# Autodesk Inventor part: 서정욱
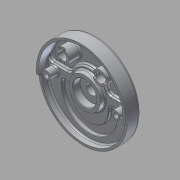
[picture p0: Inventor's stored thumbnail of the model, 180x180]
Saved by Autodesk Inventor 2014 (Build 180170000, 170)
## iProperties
Created: 2015-05
Part Number: 서정욱
Material: 알루미늄 6061
Document SubType Name: Modeling
Designer: USER
Density: 2.71 g/cm^3
Appearance: 알루미늄 - 평지
Mass: 1116.19 g
Surface Area: 1056.09 cm^2
Volume: 411.879 cm^3
Author: USER
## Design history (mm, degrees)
sketch "스케치1"
  geometry: C1 r 95 at (0, 0); 1 further point
  constraints: 1 centre point, 1 coincident
  dimensions: "d0" = 190 diameter of C1
extrude "돌출1" new body sketch "스케치1" distance "d1" = 32; taper "d2" = 0 deg
sketch "스케치2"
  geometry: L1 (0, 0)-(94.638, -8.28); L2 (-95, 0)-(95, 0); L3 (0, 0)-(-94.638, -8.28); A1 r 95 centre (0, 0) between (94.638, -8.28) and (-95, 0) reference
  constraints: 6 end point, 4 point on circle, 1 coincident, 1 horizontal, 1 midpoint
  dimensions: "d4" = 5 deg angle of L1 L2; "d5" = 5 deg angle of L3 L2
extrude "돌출2" cut sketch "스케치2" distance "d7" = 5; taper "d8" = 0 deg
sketch "스케치3"
  geometry: L1 (-89.196, 12)-(-40.249, 12); L2 (40.249, 12)-(89.196, 12); A1 r 95 centre (0, 0) between (94.638, -8.28) and (-94.638, -8.28) reference; A2 r 90 centre (0, 0) between (89.196, 12) and (-89.196, 12); A3 r 42 centre (0, 0) between (40.249, 12) and (-40.249, 12); 1 further point
  constraints: 4 end point, 4 point on circle, 2 centre point, 2 coincident, 2 horizontal
  dimensions: "d9" = 180 diameter of A2; "d10" = 84 diameter of A3; "d12" = 12 distance from line of point (0, 0) L2; "d13" = 12 distance from line of point (0, 0) L1
extrude "돌출3" cut sketch "스케치3" distance "d14" = 25; taper "d15" = 0 deg
fillet "모깎기1" dims "d16" = 10
sketch "스케치4"
  geometry: L1 (76.916, 12)-(47.117, 12) reference; L2 (-47.117, 12)-(-76.916, 12) reference; C1 r 90 at (0, 0); A1 r 10 centre (47.117, 22) between (38.056, 17.769) and (47.117, 12) reference; A2 r 42 centre (0, 0) between (38.056, 17.769) and (-38.056, 17.769) reference; A3 r 10 centre (-47.117, 22) between (-47.117, 12) and (-38.056, 17.769) reference; A4 r 10 centre (-76.916, 22) between (-86.53, 24.75) and (-76.916, 12) reference; A5 r 90 centre (0, 0) between (86.53, 24.75) and (-86.53, 24.75) reference; A6 r 10 centre (76.916, 22) between (76.916, 12) and (86.53, 24.75) reference; A7 r 95 centre (0, 0) between (94.638, -8.28) and (-94.638, -8.28) reference
  constraints: 1 centre point, 1 coincident
  dimensions: "d17" = 180 diameter of C1
extrude "돌출4" cut sketch "스케치4" distance "d18" = 18; taper "d19" = 0 deg
sketch "스케치16"
  geometry: C1 r 95 at (0, 0) reference; C2 r 25 at (0, 0)
  constraints: 1 centre point, 1 coincident
  dimensions: "d98" = 50 diameter of C2
extrude "돌출13" join sketch "스케치16" distance "d99" = 7; taper "d100" = -15 deg
sketch "스케치17"
  geometry: C1 r 35 at (0, 0); A1 r 42 centre (0, 0) between (38.056, 17.769) and (-38.056, 17.769) reference
  constraints: 1 centre point, 1 coincident
  dimensions: "d101" = 70 diameter of C1
extrude "돌출14" join sketch "스케치17" distance "d102" = 10; taper "d103" = -10 deg
hole "구멍3" diameter "d106" = 23; stored, may be unused: countersink angle "d110" = 90 deg, drill point angle "d112" = 118 deg; dims "d104" = 10, "d105" = 10, "d107" = 6, "d108" = 50, "d109" = 15, "d111" = 8
sketch "스케치18"
  geometry: C1 r 25 at (0, 0) reference; C2 r 9 at (74, 0)
  constraints: 1 centre point, 1 horizontal alignment
  dimensions: "d113" = 18 diameter of C2; "d114" = 74 distance of C1.centre C2.centre
extrude "돌출15" join sketch "스케치18" distance "d115" = 32; taper "d116" = 0 deg
hole "구멍4" sketch "스케치18" diameter "d117" = 11; stored, may be unused: countersink angle "d121" = 90 deg, drill point angle "d123" = 118 deg; dims "d118" = 6, "d119" = 18, "d120" = 11, "d122" = 8
sketch "스케치19"
  geometry: C1 r 9 at (74, 0) reference; C2 r 25 at (0, 0) reference; C3 r 15 at (40, -52)
  constraints: 1 centre point
  dimensions: "d124" = 30 diameter of C3; "d125" = 52 vertical distance of C1.centre C3.centre; "d126" = 40 horizontal distance of C2.centre C3.centre
extrude "돌출16" join sketch "스케치19" distance "d127" = 32; taper "d128" = 0 deg
hole "구멍5" diameter "d131" = 20; stored, may be unused: countersink angle "d135" = 90 deg, drill point angle "d137" = 118 deg; dims "d129" = 10, "d130" = 10, "d132" = 6, "d133" = 10, "d134" = 11, "d136" = 8
sketch "스케치20"
  geometry: L1 (-76.916, 12)-(-47.117, 12) reference; L2 (59, -19)-(41, -19); L3 (-41, -19)-(-59, -19); L4 (50, -19)-(50, -14); L5 (-50, -19)-(-50, -14); L6 (41, -19)-(41, -14); L7 (59, -19)-(59, -14); L8 (-59, -19)-(-59, -14); L9 (-41, -19)-(-41, -14); C1 r 35 at (0, 0) reference; A1 r 41 centre (0, -19) between (-41, -19) and (41, -19); A2 r 59 centre (0, -19) between (-59, -19) and (59, -19); A3 r 50 centre (0, -19) between (-50, -19) and (50, -19); A4 r 9 centre (-50, -14) between (-41, -14) and (-59, -14); A5 r 9 centre (50, -14) between (59, -14) and (41, -14); A6 r 9 centre (50, -14) between (49.84, -22.999) and (50, -23); 1 further point
  constraints: 16 end point, 15 point on circle, 7 parallel, 6 centre point, 6 tangent, 5 coincident, 2 midpoint, 2 point on line, 1 perpendicular, 1 vertical alignment
  dimensions: "d138" = 19 distance of point (0, -19) C1.centre; "d143" = 59 radius of A2; "d144" = 41 radius of A1; "d145" = 50 radius of A3; "d146" = 5 distance of L4.start L4.end; "d147" = 5 distance of L5.start L5.end; "d148" = 18 diameter of A4; "d150" = 9 radius of A5
extrude "돌출17" cut sketch "스케치20" distance "d151" = 7; taper "d152" = 0 deg
sketch "스케치21"
  geometry: L1 (0, 0)-(0, 88.845); L2 (50.912, 50.912)-(36.062, 36.062); L3 (36.062, 36.062)-(0, 0); L4 (-50.912, 50.912)-(-36.062, 36.062); L5 (-36.062, 36.062)-(0, 0); C1 r 25 at (0, 0) reference; C2 r 95 at (0, 0) reference; A1 r 72 centre (0, 0) between (50.912, 50.912) and (-50.912, 50.912); A2 r 51 centre (0, 0) between (36.062, 36.062) and (-36.062, 36.062); 1 further point
  constraints: 10 end point, 5 point on circle, 2 centre point, 2 coincident, 2 collinear, 1 vertical, 1 vertical alignment
  dimensions: "d154" = 90 deg angle of L3 L5; "d155" = 51 radius of A2; "d156" = 72 radius of A1
extrude "돌출18" join sketch "스케치21" distance "d157" = 5; taper "d158" = 0 deg
fillet "모깎기9" dims "d159" = 5
fillet "모깎기10" dims "d160" = 5
fillet "모깎기11" dims "d161" = 3
sketch "스케치22"
  geometry: C1 r 68 at (0, 0); A1 r 56 centre (0, 0) between (35.904, 42.975) and (-35.904, 42.975) reference
  constraints: 1 centre point, 1 coincident, 1 other
  dimensions: "d162" = 136 diameter of C1
feature "엠보싱2" sketch "스케치22" dims "d9" = 180, "d10" = 84, "d12" = 12, "d13" = 12, "d163" = 0.5, "d164" = 0
fillet "모깎기12" dims "d165" = 3
fillet "모깎기13" dims "d166" = 3, "d181" = 1
chamfer "모따기4" distance "d167" = 1; stored, may be unused: second distance "d168" = 2, angle "d169" = 45 deg
chamfer "모따기5" distance "d170" = 1; stored, may be unused: second distance "d171" = 2, angle "d172" = 45 deg
fillet "모깎기14" dims "d173" = 0.3
fillet "모깎기15" dims "d174" = 5
sketch "스케치23"
  geometry: L1 (-13.748, 6)-(13.748, 6); L2 (-13.748, -6)-(13.748, -6); L3 (-86, 13.748)-(-86, -13.748); L4 (-74, 13.748)-(-74, -13.748); C1 r 10 at (0, 0) reference; C2 r 10 at (-80, 0) reference; A1 r 15 centre (0, 0) between (13.748, -6) and (13.748, 6) reference; A2 r 15 centre (-80, 0) between (-74, -13.748) and (-74, 13.748) reference; 1 further point
  constraints: 8 end point, 8 point on circle, 2 parallel, 1 horizontal, 1 perpendicular
  dimensions: "d175" = 6 distance from line of L3 C2.centre; "d176" = 12 distance between parallel lines of L4 L3; "d177" = 6 distance from line of L1 C1.centre; "d178" = 12 distance between parallel lines of L2 L1
extrude "돌출19" cut sketch "스케치23" distance "d179" = 3; taper "d180" = 0 deg
chamfer "모따기6" distance "d182" = 1; stored, may be unused: second distance "d183" = 2, angle "d184" = 45 deg
node "솔리드1"
mirror "대칭1"
mirror "대칭2"
node "작업 평면1"
other parameters: "d11" = 12, "d63" = 118, "d64" = 82, "d149" = 18, "d153" = 90 deg
